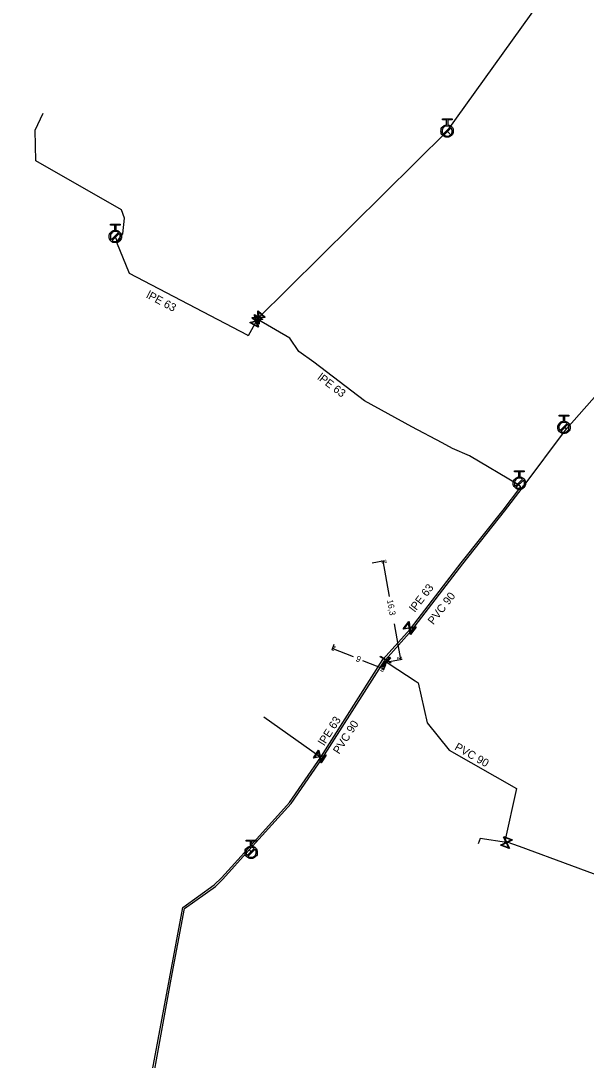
# Model space of a CAD drawing. Extents: x -641905 to -641246, y -1111750 to -1110210.
# Drawn here: x -641702.9 to -641611.1, y -1110760.9 to -1110592 of the extents above; entities that cross this region are included whole.
import ezdxf

# ---------------------------------------------------------------- set-up
doc = ezdxf.new("R2010")
doc.units = 0
for name, color, linetype in [('Default', 7, 'Continuous'), ('VP Hydrant', 7, 'Continuous'), ('VP Kótování', 7, 'Continuous'), ('VP Přípojka', 7, 'Continuous'), ('VP Řad', 7, 'Continuous'), ('VP Řad - popis', 7, 'Continuous'), ('VP Šoupě', 7, 'Continuous')]:
    doc.layers.add(name, color=color, linetype=linetype)

msp = doc.modelspace()

# ---------------------------------------------------------------- linework, layer by layer
at = {"layer": 'Default'}
for points in [[(-641633.62, -1110608.9), (-641633.26, -1110608.94), (-641633, -1110609.2), (-641632.71, -1110609.49), (-641632.71, -1110609.91), (-641632.71, -1110610.32), (-641633.01, -1110610.61), (-641633.3, -1110610.9), (-641633.72, -1110610.9), (-641634.13, -1110610.9), (-641634.42, -1110610.61), (-641634.71, -1110610.31), (-641634.71, -1110609.9), (-641634.71, -1110609.48), (-641634.42, -1110609.19), (-641634.16, -1110608.93), (-641633.8, -1110608.9)], [(-641633.2, -1110609.27), (-641633.42, -1110609.09), (-641633.71, -1110609.09), (-641634.05, -1110609.08), (-641634.29, -1110609.32), (-641634.52, -1110609.56), (-641634.53, -1110609.9), (-641634.53, -1110610.19), (-641634.35, -1110610.41)], [(-641634.22, -1110610.54), (-641634, -1110610.71), (-641633.72, -1110610.71), (-641633.38, -1110610.71), (-641633.14, -1110610.48), (-641632.9, -1110610.24), (-641632.9, -1110609.9), (-641632.9, -1110609.61), (-641633.07, -1110609.39)], [(-641687.5, -1110626.03), (-641687.14, -1110626.06), (-641686.88, -1110626.32), (-641686.59, -1110626.62), (-641686.59, -1110627.03), (-641686.59, -1110627.45), (-641686.88, -1110627.74), (-641687.18, -1110628.03), (-641687.59, -1110628.03), (-641688, -1110628.03), (-641688.3, -1110627.74), (-641688.59, -1110627.44), (-641688.59, -1110627.03), (-641688.59, -1110626.61), (-641688.3, -1110626.32), (-641688.04, -1110626.06), (-641687.68, -1110626.03)], [(-641687.08, -1110626.39), (-641687.3, -1110626.22), (-641687.59, -1110626.21), (-641687.93, -1110626.21), (-641688.17, -1110626.45), (-641688.4, -1110626.69), (-641688.4, -1110627.03), (-641688.4, -1110627.32), (-641688.23, -1110627.54)], [(-641688.1, -1110627.67), (-641687.88, -1110627.84), (-641687.59, -1110627.84), (-641687.26, -1110627.84), (-641687.02, -1110627.6), (-641686.78, -1110627.37), (-641686.78, -1110627.03), (-641686.78, -1110626.74), (-641686.95, -1110626.52)], [(-641614.65, -1110657.05), (-641614.29, -1110657.08), (-641614.03, -1110657.34), (-641613.74, -1110657.63), (-641613.74, -1110658.05), (-641613.74, -1110658.46), (-641614.03, -1110658.76), (-641614.33, -1110659.05), (-641614.74, -1110659.05), (-641615.15, -1110659.05), (-641615.45, -1110658.76), (-641615.74, -1110658.47), (-641615.74, -1110658.05), (-641615.74, -1110657.64), (-641615.45, -1110657.34), (-641615.19, -1110657.08), (-641614.83, -1110657.05)], [(-641614.23, -1110657.41), (-641614.45, -1110657.23), (-641614.74, -1110657.24), (-641615.08, -1110657.24), (-641615.32, -1110657.47), (-641615.56, -1110657.71), (-641615.55, -1110658.05), (-641615.55, -1110658.34), (-641615.38, -1110658.56)], [(-641615.25, -1110658.69), (-641615.03, -1110658.86), (-641614.74, -1110658.86), (-641614.41, -1110658.86), (-641614.17, -1110658.62), (-641613.93, -1110658.38), (-641613.93, -1110658.05), (-641613.93, -1110657.76), (-641614.1, -1110657.54)], [(-641621.88, -1110666.11), (-641621.52, -1110666.14), (-641621.26, -1110666.4), (-641620.97, -1110666.7), (-641620.97, -1110667.11), (-641620.97, -1110667.53), (-641621.26, -1110667.82), (-641621.56, -1110668.11), (-641621.97, -1110668.11), (-641622.38, -1110668.11), (-641622.68, -1110667.82), (-641622.97, -1110667.53), (-641622.97, -1110667.11), (-641622.97, -1110666.7), (-641622.68, -1110666.4), (-641622.42, -1110666.14), (-641622.06, -1110666.11)], [(-641621.46, -1110666.47), (-641621.68, -1110666.3), (-641621.97, -1110666.3), (-641622.31, -1110666.3), (-641622.55, -1110666.53), (-641622.78, -1110666.77), (-641622.78, -1110667.11), (-641622.78, -1110667.4), (-641622.61, -1110667.62)], [(-641622.48, -1110667.75), (-641622.26, -1110667.92), (-641621.97, -1110667.92), (-641621.64, -1110667.92), (-641621.4, -1110667.68), (-641621.16, -1110667.45), (-641621.16, -1110667.11), (-641621.16, -1110666.82), (-641621.33, -1110666.6)], [(-641665.45, -1110726.09), (-641665.09, -1110726.12), (-641664.83, -1110726.37), (-641664.54, -1110726.66), (-641664.53, -1110727.08), (-641664.53, -1110727.49), (-641664.82, -1110727.79), (-641665.11, -1110728.08), (-641665.53, -1110728.09), (-641665.94, -1110728.09), (-641666.23, -1110727.8), (-641666.53, -1110727.51), (-641666.53, -1110727.1), (-641666.54, -1110726.68), (-641666.25, -1110726.39), (-641665.99, -1110726.12), (-641665.63, -1110726.09)], [(-641665.03, -1110726.45), (-641665.25, -1110726.27), (-641665.54, -1110726.27), (-641665.88, -1110726.28), (-641666.12, -1110726.51), (-641666.35, -1110726.75), (-641666.35, -1110727.09), (-641666.34, -1110727.39), (-641666.17, -1110727.6)], [(-641666.04, -1110727.73), (-641665.82, -1110727.9), (-641665.53, -1110727.9), (-641665.19, -1110727.89), (-641664.96, -1110727.66), (-641664.72, -1110727.42), (-641664.72, -1110727.08), (-641664.72, -1110726.79), (-641664.9, -1110726.57)]]:
    msp.add_open_spline(points, degree=3, dxfattribs=at)
at = {"layer": 'VP Hydrant'}
for points in [[(-641633.8, -1110608.9), (-641633.8, -1110608.08), (-641634.49, -1110608.08), (-641634.48, -1110607.9), (-641632.92, -1110607.9), (-641632.92, -1110608.09), (-641633.61, -1110608.08), (-641633.62, -1110608.9)], [(-641634.35, -1110610.41), (-641633.2, -1110609.27)], [(-641633.07, -1110609.39), (-641634.22, -1110610.54)], [(-641687.68, -1110626.03), (-641687.68, -1110625.21), (-641688.37, -1110625.21), (-641688.37, -1110625.03), (-641686.81, -1110625.03), (-641686.81, -1110625.21), (-641687.5, -1110625.21), (-641687.5, -1110626.03)], [(-641688.23, -1110627.54), (-641687.08, -1110626.39)], [(-641686.95, -1110626.52), (-641688.1, -1110627.67)], [(-641614.83, -1110657.05), (-641614.83, -1110656.23), (-641615.52, -1110656.23), (-641615.52, -1110656.05), (-641613.96, -1110656.05), (-641613.96, -1110656.23), (-641614.65, -1110656.23), (-641614.65, -1110657.05)], [(-641615.38, -1110658.56), (-641614.23, -1110657.41)], [(-641614.1, -1110657.54), (-641615.25, -1110658.69)], [(-641622.06, -1110666.11), (-641622.06, -1110665.29), (-641622.75, -1110665.29), (-641622.75, -1110665.11), (-641621.19, -1110665.11), (-641621.19, -1110665.29), (-641621.88, -1110665.29), (-641621.88, -1110666.11)], [(-641622.61, -1110667.62), (-641621.46, -1110666.47)], [(-641621.33, -1110666.6), (-641622.48, -1110667.75)], [(-641665.63, -1110726.09), (-641665.64, -1110725.27), (-641666.33, -1110725.28), (-641666.33, -1110725.09), (-641664.77, -1110725.08), (-641664.77, -1110725.26), (-641665.46, -1110725.27), (-641665.45, -1110726.09)], [(-641666.17, -1110727.6), (-641665.03, -1110726.45)], [(-641664.9, -1110726.57), (-641666.04, -1110727.73)]]:
    msp.add_lwpolyline(points, dxfattribs=at)
at = {"layer": 'VP Kótování'}
for points in [[(-641645.91, -1110680.03), (-641643.86, -1110679.67)], [(-641643.08, -1110685.52), (-641644.11, -1110679.71)], [(-641642.29, -1110689.96), (-641641.26, -1110695.76)], [(-641652.1, -1110693.32), (-641652.46, -1110694.22)], [(-641648.92, -1110695.35), (-641652.37, -1110693.99)], [(-641647.44, -1110695.93), (-641644, -1110697.3)], [(-641643.73, -1110696.63), (-641644.09, -1110697.53)], [(-641643.06, -1110696.08), (-641641.01, -1110695.72)]]:
    msp.add_lwpolyline(points, dxfattribs=at)
at = {"layer": 'VP Přípojka'}
for points in [[(-641633.27, -1110610.34), (-641633.47, -1110610.11), (-641633.71, -1110609.9)], [(-641687.59, -1110627.03), (-641687.48, -1110627.48), (-641687.38, -1110627.8)], [(-641614.34, -1110658.28), (-641614.57, -1110658.14), (-641614.74, -1110658.05)], [(-641622.25, -1110667.35), (-641621.97, -1110667.11)], [(-641639.65, -1110690.75), (-641639.81, -1110690.63)], [(-641663.5, -1110705.06), (-641654.39, -1110711.52), (-641654.22, -1110711.63)], [(-641624.07, -1110725.5), (-641628.35, -1110724.82), (-641628.65, -1110725.69)], [(-641624.02, -1110725.37), (-641624.07, -1110725.5)], [(-641665.86, -1110726.69), (-641665.69, -1110726.84), (-641665.54, -1110727.08)]]:
    msp.add_lwpolyline(points, dxfattribs=at)
at = {"layer": 'VP Řad'}
for points in [[(-641664.58, -1110640.46), (-641633.71, -1110609.9), (-641600.63, -1110563.76), (-641598.45, -1110560.36), (-641594.73, -1110553.8), (-641592.83, -1110550.42), (-641585.04, -1110537.85), (-641581.85, -1110531.99), (-641576.72, -1110525.41), (-641572.32, -1110520.62), (-641569.27, -1110517.47), (-641555.1, -1110505.43), (-641544.01, -1110494.76), (-641533.36, -1110480.93), (-641531.9, -1110478.13), (-641529.81, -1110469.31), (-641527.31, -1110459.48), (-641524.97, -1110448.07), (-641523.07, -1110437.29), (-641521.61, -1110424.89), (-641523.18, -1110409.24), (-641525.76, -1110394.87), (-641527.66, -1110384.33)], [(-641664.58, -1110640.46), (-641664.68, -1110640.73), (-641664.69, -1110640.74), (-641666.03, -1110643.16), (-641666.13, -1110643.08), (-641685.29, -1110633.02), (-641687.33, -1110627.98), (-641687.38, -1110627.8), (-641687.22, -1110627.75), (-641686.36, -1110626.59), (-641686.08, -1110624.04), (-641686.61, -1110622.68), (-641700.5, -1110614.73), (-641700.63, -1110609.74), (-641699.32, -1110606.97)], [(-641678.79, -1110747.62), (-641676.64, -1110736.03), (-641671.53, -1110732.39), (-641670.37, -1110731.22), (-641666.05, -1110726.52), (-641659.3, -1110718.99), (-641654.22, -1110711.63), (-641644.15, -1110695.73), (-641639.65, -1110690.75), (-641631.42, -1110680.05), (-641624.62, -1110671.5), (-641621.76, -1110667.72), (-641622.25, -1110667.35), (-641630.08, -1110662.64), (-641632.83, -1110661.47), (-641634.51, -1110660.55), (-641639.47, -1110657.97), (-641647.12, -1110653.72), (-641655.37, -1110647.45), (-641657.78, -1110645.71), (-641659.25, -1110643.57), (-641664.58, -1110640.46)], [(-641643.86, -1110695.96), (-641643.82, -1110695.92), (-641643.71, -1110695.79), (-641639.46, -1110690.99), (-641631.18, -1110680.23), (-641624.38, -1110671.68), (-641621.52, -1110667.9), (-641614.34, -1110658.28), (-641608.15, -1110651.29), (-641606.84, -1110649.85), (-641606.72, -1110649.72)], [(-641678.5, -1110747.68), (-641676.37, -1110736.21), (-641671.33, -1110732.62), (-641670.15, -1110731.43), (-641665.86, -1110726.69), (-641659.05, -1110719.15), (-641654.01, -1110711.82), (-641643.86, -1110695.96)], [(-641643.86, -1110695.96), (-641643.6, -1110696.19), (-641643.15, -1110696.48), (-641638.88, -1110699.25), (-641638.41, -1110699.56), (-641636.96, -1110706.07), (-641633.37, -1110710.48), (-641622.45, -1110716.71), (-641624.36, -1110725.25), (-641624.02, -1110725.37)], [(-641624.02, -1110725.37), (-641622.04, -1110726.09), (-641605.04, -1110732.39), (-641592.38, -1110736.75), (-641580.95, -1110740.68), (-641580.55, -1110740.8), (-641577.05, -1110741.87), (-641571.34, -1110743.62), (-641560.51, -1110747.22), (-641550.89, -1110749.28), (-641542.88, -1110749.95), (-641530.96, -1110748.44), (-641525.88, -1110748.46), (-641513.84, -1110750.25), (-641507.42, -1110753.04), (-641507.31, -1110753.07)], [(-641677.16, -1110922.63), (-641678.03, -1110920.93), (-641690.55, -1110919.49), (-641702.17, -1110918.14), (-641702.78, -1110917.85), (-641702.94, -1110917.33), (-641701.3, -1110896.82), (-641699.93, -1110871.85), (-641699.85, -1110870.64), (-641696.18, -1110831.68), (-641685.71, -1110786.51), (-641683.53, -1110775.42), (-641678.5, -1110747.68)], [(-641698.05, -1110844.81), (-641696.45, -1110831.95), (-641696.41, -1110831.68), (-641695.92, -1110828.52), (-641690.12, -1110801.26), (-641686.1, -1110786.43), (-641683.86, -1110775.15), (-641683.88, -1110774.79), (-641683.8, -1110774.38), (-641682.47, -1110767.34), (-641678.79, -1110747.62)]]:
    msp.add_lwpolyline(points, dxfattribs=at)
at = {"layer": 'VP Šoupě'}
for points in [[(-641664.4, -1110639.13), (-641663.28, -1110640.13), (-641663.32, -1110640.18), (-641663.45, -1110640.18), (-641664.29, -1110640.23), (-641664.23, -1110641.2), (-641664.28, -1110641.25), (-641665.4, -1110640.25), (-641665.35, -1110640.2), (-641664.38, -1110640.15), (-641664.43, -1110639.31), (-641664.45, -1110639.18), (-641664.4, -1110639.13)], [(-641664.35, -1110639.31), (-641664.3, -1110640.14), (-641663.46, -1110640.09), (-641664.35, -1110639.31)], [(-641664.97, -1110639.72), (-641663.66, -1110640.45), (-641663.69, -1110640.51), (-641663.82, -1110640.54), (-641664.63, -1110640.77), (-641664.36, -1110641.7), (-641664.39, -1110641.76), (-641665.7, -1110641.03), (-641665.67, -1110640.97), (-641664.73, -1110640.71), (-641664.97, -1110639.9), (-641665.01, -1110639.78), (-641664.97, -1110639.72)], [(-641664.48, -1110641.6), (-641664.71, -1110640.79), (-641665.52, -1110641.03), (-641664.48, -1110641.6)], [(-641664.33, -1110641.08), (-641664.38, -1110640.24), (-641665.22, -1110640.29), (-641664.33, -1110641.08)], [(-641664.88, -1110639.88), (-641664.65, -1110640.68), (-641663.85, -1110640.45), (-641664.88, -1110639.88)], [(-641638.76, -1110690.49), (-641639.67, -1110691.68), (-641639.72, -1110691.64), (-641639.74, -1110691.51), (-641639.85, -1110690.68), (-641640.81, -1110690.81), (-641640.86, -1110690.77), (-641639.95, -1110689.58), (-641639.9, -1110689.62), (-641639.77, -1110690.58), (-641638.94, -1110690.47), (-641638.81, -1110690.45), (-641638.76, -1110690.49)], [(-641640.69, -1110690.7), (-641639.86, -1110690.59), (-641639.97, -1110689.76), (-641640.69, -1110690.7)], [(-641638.93, -1110690.56), (-641639.76, -1110690.67), (-641639.65, -1110691.5), (-641638.93, -1110690.56)], [(-641642.89, -1110696.36), (-641644.6, -1110695.33), (-641644.54, -1110695.22), (-641642.83, -1110696.26), (-641642.89, -1110696.36)], [(-641642.89, -1110695.48), (-641644.21, -1110696.98), (-641644.31, -1110696.9), (-641642.99, -1110695.4), (-641642.89, -1110695.48)], [(-641653.35, -1110711.31), (-641654.18, -1110712.56), (-641654.23, -1110712.52), (-641654.26, -1110712.4), (-641654.42, -1110711.57), (-641655.37, -1110711.77), (-641655.43, -1110711.73), (-641654.6, -1110710.48), (-641654.55, -1110710.52), (-641654.35, -1110711.47), (-641653.53, -1110711.3), (-641653.41, -1110711.27), (-641653.35, -1110711.31)], [(-641655.27, -1110711.66), (-641654.44, -1110711.49), (-641654.61, -1110710.66), (-641655.27, -1110711.66)], [(-641653.52, -1110711.39), (-641654.34, -1110711.56), (-641654.17, -1110712.38), (-641653.52, -1110711.39)], [(-641624.52, -1110724.54), (-641623.11, -1110725.05), (-641623.13, -1110725.11), (-641623.25, -1110725.16), (-641624.01, -1110725.52), (-641623.59, -1110726.4), (-641623.62, -1110726.46), (-641625.03, -1110725.95), (-641625.01, -1110725.89), (-641624.13, -1110725.48), (-641624.49, -1110724.72), (-641624.55, -1110724.6), (-641624.52, -1110724.54)], [(-641623.73, -1110726.32), (-641624.09, -1110725.56), (-641624.85, -1110725.92), (-641623.73, -1110726.32)], [(-641624.41, -1110724.68), (-641624.05, -1110725.44), (-641623.29, -1110725.08), (-641624.41, -1110724.68)]]:
    msp.add_lwpolyline(points, dxfattribs=at)

# ---------------------------------------------------------------- texts
at = {"layer": 'VP Kótování'}
for s, rotation, p in [('z', 100.0684, (-641643.53, -1110680.12)), ('16,3', 280.0684, (-641643.48, -1110686.1)), ('z', 158.4284, (-641651.72, -1110693.71)), ('9', 338.4284, (-641648.64, -1110696)), ('z', 280.0684, (-641641.84, -1110695.36)), ('z', 338.4284, (-641644.64, -1110697.58))]:
    msp.add_text(s, height=1, rotation=rotation, dxfattribs=at).set_placement(p)
at = {"layer": 'VP Řad - popis'}
for s, rotation, p in [('lPE 63', 332.2982, (-641682.68, -1110636.92)), ('lPE 63', 322.7652, (-641654.88, -1110650.15)), ('lPE 63', 52.428, (-641638.94, -1110688.16)), ('PVC 90', 52.3982, (-641635.95, -1110690.2)), ('lPE 63', 57.6565, (-641653.65, -1110709.86)), ('PVC 90', 57.3706, (-641651.25, -1110711.23)), ('PVC 90', 330.2947, (-641632.61, -1110710.33))]:
    msp.add_text(s, height=1.3, rotation=rotation, dxfattribs=at).set_placement(p)

doc.saveas('drawing.dxf')
